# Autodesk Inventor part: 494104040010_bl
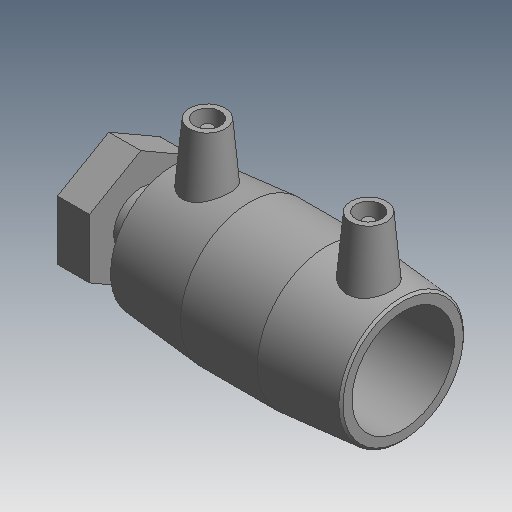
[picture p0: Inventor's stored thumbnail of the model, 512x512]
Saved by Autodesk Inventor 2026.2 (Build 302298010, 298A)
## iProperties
Created: 2017-06
Part Number: 494104040010_bl
Material: Generic
Description: PLASSON FEMALE FREE NUT TRANSITION COUPLER 40-1"
Document SubType Name: Modeling
Designer: KIM
Mass: 55.0731 g
Surface Area: 148.067 cm^2
Volume: 55.0731 cm^3
Density: 1 g/cm^3
Appearance: Default
Author: KIM
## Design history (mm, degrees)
derived "494104.ipt"
feature "Solid1::494104.ipt" dims "ScaleForDerivedMember" = 10
tag "TaggingFeature1"
body "Solid1"
other parameters: "d2" = 54 [user parameter], "d3" = 44 [user parameter], "d5" = 48.6 [user parameter], "d6" = 38 [user parameter], "d29" = 47 [user parameter], "d30" = 14 [user parameter], "d31" = 31.5 [user parameter], "d34" = 5 deg [user parameter], "d41" = 4 [user parameter], "d42" = 14 [user parameter], "d43" = 0 [user parameter], "d48" = 3 [user parameter], "d49" = 0 [user parameter], "d55" = 25 [user parameter], "d80" = 0.8 [user parameter], "d83" = 12.5 [user parameter], "d84" = 8.25 [user parameter], "d85" = 0.825 [user parameter], "d86" = 24.2328 [user parameter], "d87" = 30.291 [user parameter], "d88" = 33.291 [user parameter], "d89" = 54 [user parameter], "d96" = 21.2037 [user parameter], "d97" = 0 [user parameter], "d98" = 3.0291 [user parameter], "d99" = 3.0291 [user parameter], "d106" = 0 [user parameter], "d107" = 6.5 [user parameter], "L_" = 115 [user parameter], "L_1" = 44 [user parameter], "D_1" = 54 [user parameter], "A_" = 47 [user parameter], "d_2" = 12 [user parameter], "L_2" = 25 [user parameter], "D_" = 19 [user parameter], "G_" = 30.291 [user parameter], "d102" = 33.291 [user parameter]
